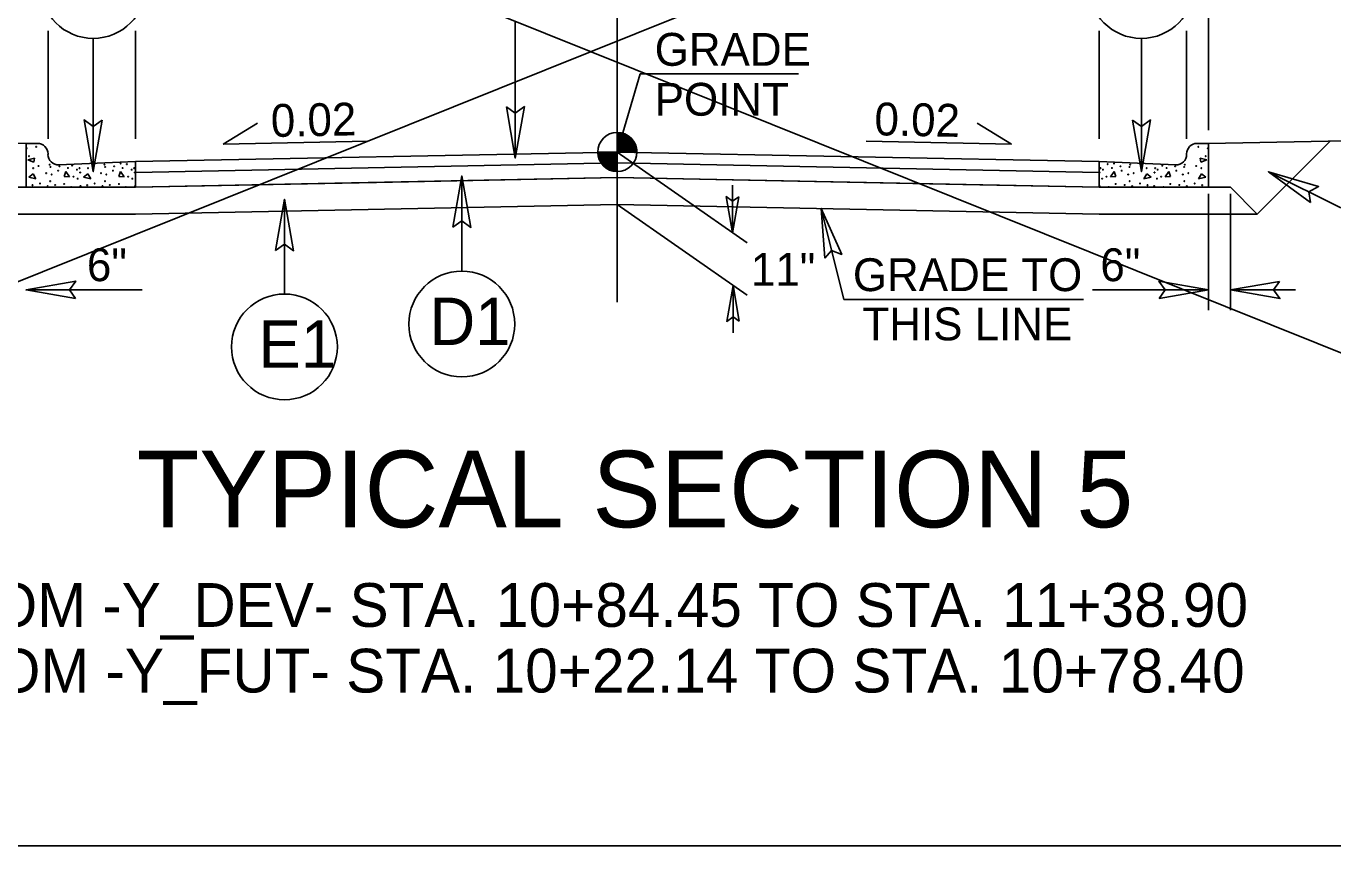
# Model space of a CAD drawing. Extents: x 1487909 to 1489267, y 497866 to 499814.
# Drawn here: x 1489209.2 to 1489239.04, y 498144.27 to 498163 of the extents above; entities that cross this region are included whole.
import ezdxf

# ---------------------------------------------------------------- set-up
doc = ezdxf.new("R2010")
doc.units = 0
for name, color, linetype in [('Old_Level_10', 7, 'Continuous'), ('Prop Dimension', 7, 'Continuous'), ('Prop Dimension Text', 7, 'Continuous'), ('Prop Shade Light', 7, 'Continuous'), ('Prop Terminator CELL', 7, 'Continuous'), ('Scratch_Level_3', 7, 'Continuous'), ('Typical Curb CELL', 7, 'Continuous'), ('Typical Detail Wedge2 CELL', 7, 'Continuous'), ('Typical Grade Point Symbol CELL', 7, 'Continuous'), ('Typical Hinge Slope Arterial CELL', 7, 'Continuous'), ('Typical ID Circle CELL', 7, 'Continuous'), ('Typical Pavement Slope CELL', 7, 'Continuous'), ('Typical Pavement Slope Information CELL', 7, 'Continuous'), ('Typical Terminator CELL', 7, 'Continuous'), ('Typical Text Grade Point CELL', 7, 'Continuous'), ('Typical Text ID Circle CELL', 7, 'Continuous')]:
    doc.layers.add(name, color=color, linetype=linetype)

msp = doc.modelspace()

# ---------------------------------------------------------------- linework, layer by layer
at = {"layer": 'Old_Level_10'}
for p, q in [((1489222.699, 498159.874), (1489211.699, 498159.654)), ((1489211.699, 498159.654), (1489211.699, 498159.32)), ((1489222.699, 498159.874), (1489222.699, 498159.54)), ((1489233.699, 498159.654), (1489222.699, 498159.874)), ((1489222.699, 498159.874), (1489222.699, 498159.874)), ((1489222.699, 498159.54), (1489222.699, 498159.874)), ((1489233.699, 498159.32), (1489233.699, 498159.654)), ((1489211.699, 498159.32), (1489217.198, 498159.43)), ((1489217.198, 498159.43), (1489222.699, 498159.54)), ((1489222.699, 498159.54), (1489230.199, 498159.39)), ((1489230.199, 498159.39), (1489233.699, 498159.32))]:
    msp.add_line(p, q, dxfattribs=at)
at = {"layer": 'Prop Dimension'}
for p, q in [((1489222.699, 498156.69), (1489222.699, 498174.752)), ((1489236.199, 498160.621), (1489236.199, 498169.227)), ((1489209.699, 498160.424), (1489209.699, 498162.894)), ((1489211.699, 498160.424), (1489211.699, 498162.894)), ((1489233.699, 498160.424), (1489233.699, 498162.894)), ((1489235.699, 498160.424), (1489235.699, 498162.894)), ((1489236.198, 498156.514), (1489236.198, 498159.168)), ((1489236.698, 498156.514), (1489236.698, 498159.168)), ((1489227.872, 498156.751), (1489227.356, 498158.834)), ((1489209.199, 498156.974), (1489211.847, 498156.974)), ((1489236.198, 498156.974), (1489233.55, 498156.974)), ((1489238.185, 498156.974), (1489236.698, 498156.974)), ((1489233.345, 498156.751), (1489227.872, 498156.751))]:
    msp.add_line(p, q, dxfattribs=at)
at = {"layer": 'Prop Dimension Text'}
for p in [(1489222.699, 498160.124), (1489226.839, 498161.913)]:
    msp.add_line(p, (1489223.224, 498161.913), dxfattribs=at)
at = {"layer": 'Prop Shade Light'}
for p, q in [((1489222.699, 498160.124), (1489211.699, 498159.904)), ((1489222.699, 498159.874), (1489222.699, 498160.124)), ((1489233.699, 498159.904), (1489222.699, 498160.124)), ((1489222.699, 498160.124), (1489222.699, 498159.874)), ((1489211.699, 498159.904), (1489211.699, 498159.654)), ((1489211.699, 498159.654), (1489222.699, 498159.874)), ((1489222.699, 498159.874), (1489233.699, 498159.654)), ((1489233.699, 498159.654), (1489233.699, 498159.904))]:
    msp.add_line(p, q, dxfattribs=at)
at = {"layer": 'Prop Terminator CELL'}
for points in [[(1489227.438, 498157.696), (1489227.356, 498158.834), (1489227.822, 498157.784), (1489227.593, 498157.876)], [(1489210.324, 498156.78), (1489209.199, 498156.974), (1489210.33, 498157.174), (1489210.186, 498156.974)], [(1489235.073, 498156.78), (1489236.198, 498156.974), (1489235.067, 498157.174), (1489235.211, 498156.974)], [(1489237.823, 498157.167), (1489236.698, 498156.974), (1489237.829, 498156.774), (1489237.686, 498156.974)]]:
    msp.add_lwpolyline(points, close=True, dxfattribs=at)
at = {"layer": 'Scratch_Level_3'}
for p, q in [((1489176.952, 498144.269), (1489267.234, 498180.571)), ((1489267.234, 498144.269), (1489176.952, 498180.571))]:
    msp.add_line(p, q, dxfattribs=at)
msp.add_lwpolyline([(1489176.952, 498180.571), (1489267.234, 498180.571), (1489267.234, 498144.269), (1489176.952, 498144.269)], close=True, dxfattribs=at)
at = {"layer": 'Typical Curb CELL'}
for p, q in [((1489209.199, 498159.32), (1489209.199, 498160.32)), ((1489209.199, 498160.32), (1489209.459, 498160.32)), ((1489236.198, 498160.32), (1489235.938, 498160.32)), ((1489236.198, 498159.32), (1489236.198, 498160.32)), ((1489209.235, 498159.942), (1489209.389, 498159.987)), ((1489209.373, 498159.896), (1489209.235, 498159.942)), ((1489209.389, 498159.987), (1489209.373, 498159.896)), ((1489209.699, 498160.07), (1489209.699, 498160.081)), ((1489235.698, 498160.07), (1489235.698, 498160.081)), ((1489236.008, 498159.987), (1489236.024, 498159.896)), ((1489236.162, 498159.942), (1489236.008, 498159.987)), ((1489236.024, 498159.896), (1489236.162, 498159.942)), ((1489209.361, 498159.623), (1489209.258, 498159.548)), ((1489209.424, 498159.509), (1489209.361, 498159.623)), ((1489211.699, 498159.904), (1489209.948, 498159.831)), ((1489210.103, 498159.68), (1489210.069, 498159.566)), ((1489210.188, 498159.56), (1489210.103, 498159.68)), ((1489210.61, 498159.623), (1489210.507, 498159.548)), ((1489210.673, 498159.509), (1489210.61, 498159.623)), ((1489211.352, 498159.68), (1489211.317, 498159.566)), ((1489211.438, 498159.56), (1489211.352, 498159.68)), ((1489211.699, 498159.32), (1489211.699, 498159.904)), ((1489233.699, 498159.32), (1489233.699, 498159.904)), ((1489233.699, 498159.904), (1489235.449, 498159.831)), ((1489233.959, 498159.56), (1489234.045, 498159.68)), ((1489234.045, 498159.68), (1489234.08, 498159.566)), ((1489234.724, 498159.509), (1489234.787, 498159.623)), ((1489234.787, 498159.623), (1489234.89, 498159.548)), ((1489235.209, 498159.56), (1489235.294, 498159.68)), ((1489235.294, 498159.68), (1489235.328, 498159.566)), ((1489235.973, 498159.509), (1489236.036, 498159.623)), ((1489236.036, 498159.623), (1489236.139, 498159.548)), ((1489209.199, 498159.32), (1489211.699, 498159.32)), ((1489209.258, 498159.548), (1489209.424, 498159.509)), ((1489210.069, 498159.566), (1489210.188, 498159.56)), ((1489210.507, 498159.548), (1489210.673, 498159.509)), ((1489211.317, 498159.566), (1489211.438, 498159.56)), ((1489236.198, 498159.32), (1489233.699, 498159.32)), ((1489234.08, 498159.566), (1489233.959, 498159.56)), ((1489234.89, 498159.548), (1489234.724, 498159.509)), ((1489235.328, 498159.566), (1489235.209, 498159.56)), ((1489236.139, 498159.548), (1489235.973, 498159.509))]:
    msp.add_line(p, q, dxfattribs=at)
for centre in [(1489209.212, 498160.21), (1489209.429, 498160.244), (1489235.968, 498160.244), (1489236.185, 498160.21), (1489209.264, 498160.028), (1489236.133, 498160.028), (1489209.361, 498159.754), (1489209.481, 498159.805), (1489209.658, 498159.64), (1489209.738, 498159.834), (1489209.755, 498159.783), (1489209.783, 498159.612), (1489209.932, 498159.697), (1489209.96, 498159.799), (1489210.154, 498159.76), (1489210.251, 498159.814), (1489210.36, 498159.72), (1489210.416, 498159.754), (1489210.433, 498159.658), (1489210.61, 498159.754), (1489210.73, 498159.805), (1489210.907, 498159.64), (1489210.987, 498159.834), (1489211.004, 498159.783), (1489211.032, 498159.612), (1489211.181, 498159.697), (1489211.209, 498159.799), (1489211.358, 498159.862), (1489211.403, 498159.76), (1489211.5, 498159.845), (1489211.609, 498159.72), (1489211.665, 498159.754), (1489211.682, 498159.658), (1489233.715, 498159.658), (1489233.732, 498159.754), (1489233.788, 498159.72), (1489233.897, 498159.845), (1489233.994, 498159.76), (1489234.039, 498159.862), (1489234.188, 498159.799), (1489234.216, 498159.697), (1489234.365, 498159.612), (1489234.393, 498159.783), (1489234.41, 498159.834), (1489234.49, 498159.64), (1489234.667, 498159.805), (1489234.787, 498159.754), (1489234.964, 498159.658), (1489234.981, 498159.754), (1489235.037, 498159.72), (1489235.146, 498159.814), (1489235.243, 498159.76), (1489235.437, 498159.799), (1489235.465, 498159.697), (1489235.614, 498159.612), (1489235.642, 498159.783), (1489235.659, 498159.834), (1489235.739, 498159.64), (1489235.916, 498159.805), (1489236.036, 498159.754), (1489209.344, 498159.366), (1489209.515, 498159.406), (1489209.692, 498159.343), (1489209.749, 498159.458), (1489209.863, 498159.372), (1489210.069, 498159.395), (1489210.228, 498159.326), (1489210.28, 498159.56), (1489210.376, 498159.515), (1489210.439, 498159.349), (1489210.593, 498159.366), (1489210.764, 498159.406), (1489210.941, 498159.343), (1489210.998, 498159.458), (1489211.112, 498159.372), (1489211.318, 498159.395), (1489211.477, 498159.326), (1489211.529, 498159.56), (1489211.625, 498159.515), (1489211.688, 498159.349), (1489233.709, 498159.349), (1489233.772, 498159.515), (1489233.868, 498159.56), (1489233.92, 498159.326), (1489234.079, 498159.395), (1489234.285, 498159.372), (1489234.399, 498159.458), (1489234.456, 498159.343), (1489234.633, 498159.406), (1489234.804, 498159.366), (1489234.958, 498159.349), (1489235.021, 498159.515), (1489235.117, 498159.56), (1489235.169, 498159.326), (1489235.328, 498159.395), (1489235.534, 498159.372), (1489235.648, 498159.458), (1489235.705, 498159.343), (1489235.882, 498159.406), (1489236.053, 498159.366)]:
    msp.add_circle(centre, 0.00802, dxfattribs=at)
for centre, start, end in [((1489209.459, 498160.081), 0, 90), ((1489235.938, 498160.081), 90, 180), ((1489209.938, 498160.07), 180, 272.3845), ((1489235.459, 498160.07), 267.6155, 0)]:
    msp.add_arc(centre, 0.24, start, end, dxfattribs=at)
at = {"layer": 'Typical Detail Wedge2 CELL'}
for p, q in [((1489222.699, 498160.124), (1489225.663, 498158.048)), ((1489225.331, 498159.364), (1489225.331, 498158.28)), ((1489222.699, 498158.927), (1489225.662, 498156.852)), ((1489225.342, 498157.077), (1489225.342, 498155.992))]:
    msp.add_line(p, q, dxfattribs=at)
at = {"layer": 'Typical Grade Point Symbol CELL'}
for p, q in [((1489222.699, 498160.124), (1489222.699, 498160.571)), ((1489222.251, 498160.124), (1489222.699, 498160.124)), ((1489222.698, 498159.676), (1489222.699, 498160.124)), ((1489222.699, 498160.124), (1489222.698, 498159.676)), ((1489223.146, 498160.124), (1489222.699, 498160.124))]:
    msp.add_line(p, q, dxfattribs=at)
for points in [[(1489222.703, 498160.571), (1489222.703, 498160.571), (1489222.703, 498160.124)], [(1489222.711, 498160.571), (1489222.711, 498160.124)], [(1489222.72, 498160.57), (1489222.72, 498160.124)], [(1489222.729, 498160.57), (1489222.729, 498160.124)], [(1489222.738, 498160.569), (1489222.738, 498160.124)], [(1489222.747, 498160.568), (1489222.747, 498160.124)], [(1489222.756, 498160.567), (1489222.756, 498160.124)], [(1489222.765, 498160.566), (1489222.765, 498160.124)], [(1489222.774, 498160.565), (1489222.774, 498160.124)], [(1489222.783, 498160.563), (1489222.783, 498160.124)], [(1489222.792, 498160.561), (1489222.792, 498160.124)], [(1489222.801, 498160.559), (1489222.801, 498160.124)], [(1489222.81, 498160.557), (1489222.81, 498160.124)], [(1489222.819, 498160.554), (1489222.819, 498160.124)], [(1489222.828, 498160.552), (1489222.828, 498160.124)], [(1489222.837, 498160.549), (1489222.837, 498160.124)], [(1489222.846, 498160.546), (1489222.846, 498160.124)], [(1489222.855, 498160.543), (1489222.855, 498160.124)], [(1489222.864, 498160.539), (1489222.864, 498160.124)], [(1489222.873, 498160.535), (1489222.873, 498160.124)], [(1489222.882, 498160.531), (1489222.882, 498160.124)], [(1489222.891, 498160.527), (1489222.891, 498160.124)], [(1489222.899, 498160.524), (1489222.899, 498160.124)], [(1489222.908, 498160.519), (1489222.908, 498160.124)], [(1489222.917, 498160.514), (1489222.917, 498160.124)], [(1489222.926, 498160.509), (1489222.926, 498160.124)], [(1489222.935, 498160.504), (1489222.935, 498160.124)], [(1489222.944, 498160.498), (1489222.944, 498160.124)], [(1489222.953, 498160.492), (1489222.953, 498160.124)], [(1489222.962, 498160.485), (1489222.962, 498160.124)], [(1489222.971, 498160.479), (1489222.971, 498160.124)], [(1489222.98, 498160.472), (1489222.98, 498160.124)], [(1489222.989, 498160.464), (1489222.989, 498160.124)], [(1489222.998, 498160.456), (1489222.998, 498160.124)], [(1489223.007, 498160.448), (1489223.007, 498160.124)], [(1489223.016, 498160.439), (1489223.016, 498160.124)], [(1489223.025, 498160.43), (1489223.025, 498160.124)], [(1489223.034, 498160.42), (1489223.034, 498160.124)], [(1489223.043, 498160.409), (1489223.043, 498160.124)], [(1489223.052, 498160.398), (1489223.052, 498160.124)], [(1489223.061, 498160.386), (1489223.061, 498160.124)], [(1489223.07, 498160.373), (1489223.07, 498160.124)], [(1489223.078, 498160.359), (1489223.078, 498160.124)], [(1489223.087, 498160.344), (1489223.087, 498160.124)], [(1489223.096, 498160.329), (1489223.096, 498160.124)], [(1489223.105, 498160.31), (1489223.105, 498160.124)], [(1489223.114, 498160.289), (1489223.114, 498160.124)], [(1489223.123, 498160.264), (1489223.123, 498160.124)], [(1489223.132, 498160.233), (1489223.132, 498160.124)], [(1489222.253, 498160.124), (1489222.253, 498160.075)], [(1489222.262, 498160.124), (1489222.262, 498160.022)], [(1489222.271, 498160.124), (1489222.271, 498159.99)], [(1489222.28, 498160.124), (1489222.28, 498159.964)], [(1489222.289, 498160.124), (1489222.289, 498159.943)], [(1489222.298, 498160.124), (1489222.298, 498159.924)], [(1489222.307, 498160.124), (1489222.307, 498159.907)], [(1489222.316, 498160.124), (1489222.316, 498159.891)], [(1489222.325, 498160.124), (1489222.325, 498159.877)], [(1489222.334, 498160.124), (1489222.334, 498159.864)], [(1489222.342, 498160.124), (1489222.342, 498159.852)], [(1489222.351, 498160.124), (1489222.351, 498159.841)], [(1489222.36, 498160.124), (1489222.36, 498159.83)], [(1489222.369, 498160.124), (1489222.369, 498159.82)], [(1489222.378, 498160.124), (1489222.378, 498159.81)], [(1489222.387, 498160.124), (1489222.387, 498159.801)], [(1489222.396, 498160.124), (1489222.396, 498159.793)], [(1489222.405, 498160.124), (1489222.405, 498159.785)], [(1489222.414, 498160.124), (1489222.414, 498159.778)], [(1489222.423, 498160.124), (1489222.423, 498159.771)], [(1489222.432, 498160.124), (1489222.432, 498159.764)], [(1489222.441, 498160.124), (1489222.441, 498159.758)], [(1489222.45, 498160.124), (1489222.45, 498159.752)], [(1489222.459, 498160.124), (1489222.459, 498159.746)], [(1489222.468, 498160.124), (1489222.468, 498159.74)], [(1489222.477, 498160.124), (1489222.477, 498159.735)], [(1489222.486, 498160.124), (1489222.486, 498159.73)], [(1489222.495, 498160.124), (1489222.495, 498159.725)], [(1489222.504, 498160.124), (1489222.504, 498159.721)], [(1489222.513, 498160.124), (1489222.513, 498159.717)], [(1489222.522, 498160.124), (1489222.522, 498159.713)], [(1489222.53, 498160.124), (1489222.53, 498159.709)], [(1489222.539, 498160.124), (1489222.539, 498159.705)], [(1489222.548, 498160.124), (1489222.548, 498159.702)], [(1489222.557, 498160.124), (1489222.557, 498159.699)], [(1489222.566, 498160.124), (1489222.566, 498159.696)], [(1489222.575, 498160.124), (1489222.575, 498159.694)], [(1489222.584, 498160.124), (1489222.584, 498159.691)], [(1489222.593, 498160.124), (1489222.593, 498159.689)], [(1489222.602, 498160.124), (1489222.602, 498159.687)], [(1489222.611, 498160.124), (1489222.611, 498159.685)], [(1489222.62, 498160.124), (1489222.62, 498159.683)], [(1489222.629, 498160.124), (1489222.629, 498159.682)], [(1489222.638, 498160.124), (1489222.638, 498159.68)], [(1489222.647, 498160.124), (1489222.647, 498159.679)], [(1489222.656, 498160.124), (1489222.656, 498159.678)], [(1489222.665, 498160.124), (1489222.665, 498159.677)], [(1489222.674, 498160.124), (1489222.674, 498159.677)], [(1489222.683, 498160.124), (1489222.683, 498159.676)], [(1489222.692, 498160.124), (1489222.692, 498159.676), (1489222.692, 498159.676)], [(1489223.141, 498160.187), (1489223.141, 498160.124)]]:
    msp.add_lwpolyline(points, dxfattribs=at)
msp.add_circle((1489222.698, 498160.124), 0.448, dxfattribs=at)
for start, end in [(359.9905, 89.9905), (179.9905, 269.9905)]:
    msp.add_arc((1489222.698, 498160.124), 0.448, start, end, dxfattribs=at)
at = {"layer": 'Typical ID Circle CELL'}
for p, q in [((1489220.369, 498163.108), (1489220.369, 498159.985)), ((1489210.731, 498162.721), (1489210.731, 498159.677)), ((1489234.666, 498162.721), (1489234.666, 498159.677)), ((1489239.223, 498158.85), (1489237.566, 498159.674)), ((1489219.148, 498157.402), (1489219.148, 498159.58)), ((1489215.098, 498156.88), (1489215.098, 498159.046))]:
    msp.add_line(p, q, dxfattribs=at)
for centre in [(1489210.731, 498163.929), (1489234.666, 498163.929), (1489219.148, 498156.194), (1489215.098, 498155.672)]:
    msp.add_circle(centre, 1.208, dxfattribs=at)
at = {"layer": 'Typical Pavement Slope CELL'}
for p, q in [((1489209.199, 498160.32), (1489195.199, 498160.6)), ((1489236.198, 498160.32), (1489250.198, 498160.6)), ((1489238.98, 498160.376), (1489237.311, 498158.707)), ((1489211.699, 498159.904), (1489222.699, 498160.124)), ((1489233.699, 498159.904), (1489222.699, 498160.124)), ((1489211.699, 498159.654), (1489222.699, 498159.874)), ((1489233.699, 498159.654), (1489222.699, 498159.874)), ((1489209.199, 498159.32), (1489208.699, 498159.32)), ((1489211.699, 498159.32), (1489222.699, 498159.54)), ((1489233.699, 498159.32), (1489222.699, 498159.54)), ((1489236.198, 498159.32), (1489236.698, 498159.32)), ((1489236.698, 498159.32), (1489237.311, 498158.707)), ((1489211.699, 498158.707), (1489222.699, 498158.927)), ((1489233.699, 498158.707), (1489222.699, 498158.927)), ((1489211.699, 498158.707), (1489208.086, 498158.707)), ((1489233.699, 498158.707), (1489237.311, 498158.707))]:
    msp.add_line(p, q, dxfattribs=at)
at = {"layer": 'Typical Pavement Slope Information CELL'}
for p, q in [((1489213.696, 498160.306), (1489214.479, 498160.78)), ((1489231.701, 498160.306), (1489230.918, 498160.78)), ((1489213.696, 498160.306), (1489217.012, 498160.373)), ((1489231.701, 498160.306), (1489228.385, 498160.373))]:
    msp.add_line(p, q, dxfattribs=at)
at = {"layer": 'Typical Terminator CELL'}
for points in [[(1489220.167, 498161.157), (1489220.369, 498159.985), (1489220.577, 498161.163), (1489220.369, 498161.014)], [(1489210.933, 498160.849), (1489210.731, 498159.677), (1489210.523, 498160.856), (1489210.731, 498160.706)], [(1489210.933, 498160.849), (1489210.731, 498159.677), (1489210.523, 498160.856), (1489210.731, 498160.706)], [(1489234.464, 498160.849), (1489234.666, 498159.677), (1489234.874, 498160.856), (1489234.666, 498160.706)], [(1489234.464, 498160.849), (1489234.666, 498159.677), (1489234.874, 498160.856), (1489234.666, 498160.706)], [(1489238.525, 498158.972), (1489237.566, 498159.674), (1489238.713, 498159.336), (1489238.487, 498159.216)], [(1489218.946, 498158.408), (1489219.148, 498159.58), (1489219.356, 498158.401), (1489219.148, 498158.551)], [(1489214.897, 498157.874), (1489215.098, 498159.046), (1489215.307, 498157.868), (1489215.098, 498158.017)], [(1489225.472, 498159.1), (1489225.331, 498158.28), (1489225.185, 498159.105), (1489225.331, 498159)], [(1489225.483, 498156.256), (1489225.342, 498157.077), (1489225.196, 498156.252), (1489225.342, 498156.357)]]:
    msp.add_lwpolyline(points, close=True, dxfattribs=at)

# ---------------------------------------------------------------- texts
at = {"layer": 'Prop Dimension Text'}
for s, p in [('6"', (1489210.587, 498157.173)), ('6"', (1489233.729, 498157.173)), ('11"', (1489225.749, 498157.069)), ('GRADE TO', (1489228.078, 498156.946)), ('THIS LINE', (1489228.296, 498155.821))]:
    msp.add_text(s, height=0.75, dxfattribs=at).set_placement(p)
at = {"layer": 'Typical Hinge Slope Arterial CELL'}
for s, p in [('FROM -Y_DEV- STA. 10+84.45 TO STA. 11+38.90', (1489206.629, 498149.274)), ('FROM -Y_FUT- STA. 10+22.14 TO STA. 10+78.40', (1489206.702, 498147.774))]:
    msp.add_text(s, height=1, dxfattribs=at).set_placement(p)
at = {"layer": 'Typical Pavement Slope CELL'}
msp.add_text('TYPICAL SECTION 5', height=1.75, dxfattribs=at).set_placement((1489211.724, 498151.549))
at = {"layer": 'Typical Pavement Slope Information CELL'}
for rotation, p in [(1.1457, (1489214.794, 498160.467)), (358.8543, (1489228.565, 498160.508))]:
    msp.add_text('0.02', height=0.75, rotation=rotation, dxfattribs=at).set_placement(p)
at = {"layer": 'Typical Text Grade Point CELL'}
for s, p in [('GRADE', (1489223.552, 498162.095)), ('POINT', (1489223.552, 498160.954))]:
    msp.add_text(s, height=0.75, dxfattribs=at).set_placement(p)
at = {"layer": 'Typical Text ID Circle CELL'}
for s, p in [('D1', (1489218.409, 498155.715)), ('E1', (1489214.507, 498155.193))]:
    msp.add_text(s, height=1.0817, dxfattribs=at).set_placement(p)

doc.saveas('drawing.dxf')
